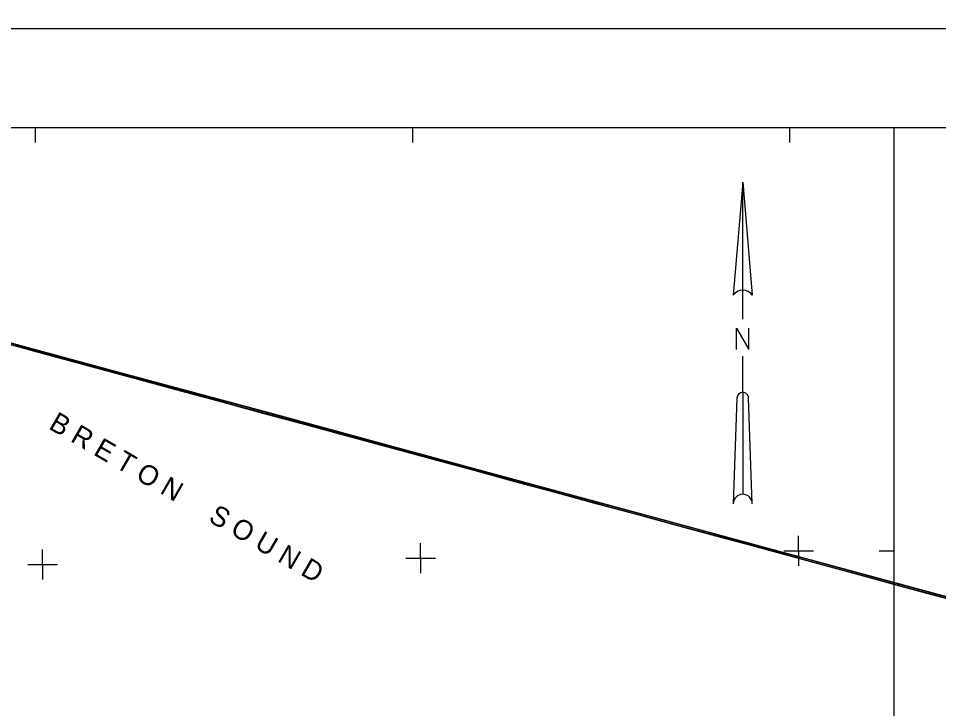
# Model space of a CAD drawing. Extents: x -8691643 to 6155447, y 250003 to 4279621.
# Drawn here: x 3596753 to 3790305, y 867885 to 1013116 of the extents above; entities that cross this region are included whole.
import ezdxf

# ---------------------------------------------------------------- set-up
doc = ezdxf.new("R2010")
doc.units = 0
for name, color, linetype in [('G-ANNO-NPLT', 7, 'Continuous'), ('V-ANNO-SYMB', 7, 'Continuous'), ('V-GRID-MAJR', 7, 'Continuous'), ('V-TOPO-GNAM-IDEN', 7, 'Continuous'), ('V-TOPO-SHOR', 7, 'Continuous')]:
    doc.layers.add(name, color=color, linetype=linetype)

msp = doc.modelspace()

# ---------------------------------------------------------------- linework, layer by layer
at = {"layer": 'G-ANNO-NPLT'}
msp.add_lwpolyline([(3045110.255, 1011024.8640000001), (3965150.255, 1011024.8640000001), (3965150.255, 404634.86400000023), (3045110.255, 404634.86400000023)], close=True, dxfattribs=at)
at = {"layer": 'V-ANNO-SYMB'}
for p, q in [((3944240.255, 990114.8640000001), (3113067.755, 990114.8640000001)), ((3780960.255, 655554.8639999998), (3780960.255, 990114.8640000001)), ((3749110.8750281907, 978653.914), (3747117.095028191, 954845.819)), ((3749110.8750281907, 978653.914), (3751104.6580281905, 954845.819)), ((3749110.8750281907, 955901.3520000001), (3749110.8750281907, 978653.914)), ((3749110.8750281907, 949802.726), (3749110.8750281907, 955901.3520000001)), ((3749110.8750281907, 934438.882), (3749110.8750281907, 942062.164)), ((3747891.1500281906, 933219.1560000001), (3747117.095028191, 910982.632)), ((3749110.8750281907, 934438.882), (3749110.8750281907, 912976.414)), ((3751104.6580281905, 910982.632), (3750330.6000281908, 933219.1560000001))]:
    msp.add_line(p, q, dxfattribs=at)
msp.add_lwpolyline([(3747797.325028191, 943423.002), (3747797.325028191, 947926.6020000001), (3750424.4250281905, 943423.002), (3750424.4250281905, 947926.6020000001)], dxfattribs=at)
for centre, radius, start, end in [((3749110.8761259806, 953490.5693583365), 2410.7812505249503, 89.9999994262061, 145.79454109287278), ((3749110.8761259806, 953490.5693583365), 2410.7812505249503, 34.20545775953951, 89.98882442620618), ((3749110.876124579, 933219.1568588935), 1219.724996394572, 90.00330555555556, 180), ((3749110.876124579, 933219.1568588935), 1219.724996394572, 0, 90.00330555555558), ((3749110.876128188, 910982.6318625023), 1993.7812500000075, 90, 180), ((3749110.876128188, 910982.6318625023), 1993.7812500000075, 0, 90), ((3749110.876128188, 910982.6318625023), 1993.7812500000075, 0, 90)]:
    msp.add_arc(centre, radius, start, end, dxfattribs=at)
at = {"layer": 'V-GRID-MAJR'}
for p, q in [((3600384.133, 986978.3640000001), (3600384.133, 990114.8640000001)), ((3679703.858, 986978.3640000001), (3679703.858, 990114.8640000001)), ((3759020.431, 986978.3640000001), (3759020.431, 990114.8640000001)), ((3760871.52, 901085.511), (3760871.52, 904222.011)), ((3681356.6350000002, 899552.922), (3681356.6350000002, 902689.422)), ((3601838.6, 898193.817), (3601838.6, 901330.317)), ((3757735.02, 901085.511), (3760871.52, 901085.511)), ((3760871.52, 901085.511), (3764008.02, 901085.511)), ((3760871.52, 901085.511), (3760871.52, 897949.011)), ((3777823.755, 901085.511), (3780960.255, 901085.511)), ((3598702.1, 898193.817), (3601838.6, 898193.817)), ((3601838.6, 898193.817), (3604975.1, 898193.817)), ((3601838.6, 898193.817), (3601838.6, 895057.317)), ((3678220.1350000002, 899552.922), (3681356.6350000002, 899552.922)), ((3681356.6350000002, 899552.922), (3684493.1350000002, 899552.922)), ((3681356.6350000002, 899552.922), (3681356.6350000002, 896416.422))]:
    msp.add_line(p, q, dxfattribs=at)
at = {"layer": 'V-TOPO-SHOR'}
msp.add_spline([(3435608.936, 990123.92), (3435590.219, 989816.573), (3435602.943, 989650.9890000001), (3435628.39, 989383.507), (3435679.285, 989154.237), (3435615.667, 988912.23), (3435628.39, 988810.332), (3435692.009, 988708.434), (3435946.482, 988097.0480000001), (3435946.482, 988097.0480000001), (3435870.14, 987969.675), (3435984.653, 987778.617), (3436264.574, 987485.661)], degree=3, dxfattribs=at)

# ---------------------------------------------------------------- texts
at = {"layer": 'V-TOPO-GNAM-IDEN'}
msp.add_text('B R E T O N     S O U N D', height=4182, rotation=329.9058505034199, dxfattribs=at).set_placement((3602908.955214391, 926883.4340106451))

doc.saveas('drawing.dxf')
